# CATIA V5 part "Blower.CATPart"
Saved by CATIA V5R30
Part number: Blower
Bounding box of the stored display mesh (mm): x -55 to 55, y -55 to 55, z -25 to 72.5
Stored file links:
  D:\CADCIM\CATIA\2020\Ch12\c12_catia_v5_6r2019_tut\c12Tut1\Blower.CATPart
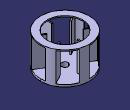
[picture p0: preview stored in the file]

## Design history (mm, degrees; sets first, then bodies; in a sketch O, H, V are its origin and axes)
Body1 (main body)
  Sketch1 on xy-plane, origin (0, 0, 0), H (1, 0, 0), V (0, 1, 0)
    circle A1 centre (0, 0) radius 55
    point P1 (0, 0)
    radius A1 = 55
    coincidence: P1 H, P1 O
  Pad1: profile Sketch1, direction (0, 0, 1), length 5
  Sketch2 on face of Pad1, origin (0, 0, 5), H (1, 0, 0), V (0, 1, 0)
    line L1 (0, 55) -> (0, 30)
    point P1 (0, 55)
    projected arc E1 centre (0, 0) radius 55 from (18.8111, 51.6831) to (0, 55) ccw from edge of Pad1
    line L2 (2.5, 53.4416) -> (2.5, 30)
    arc A1 centre (0, 0) radius 53.5 from (18.2981, 50.2736) to (2.5, 53.4416) ccw
    line L3 (0, 30) -> (2.5, 30)
    line L4 (18.2981, 50.2736) -> (18.8111, 51.6831)
    length L1 = 25
    distance L1 L2 = 2.5
    distance E1 A1 = 1.5
    angle L4 L1 = 20
    coincidence: P1 V, O L4
    vertical: L1 V
    concentricity: E1 A1
    horizontal: L3 H
  Pad2: profile Sketch2, direction (0, 0, 1), length 65
  CircPattern1: of Pad2, instances 6, angular step 60, axis from face of Pad1 from Sketch1.A1
  Sketch3 on face of Pad1, origin (0, 0, 0), H (1, 0, 0), V (0, -1, 0)
    circle A1 centre (0, 0) radius 15
    radius A1 = 15
  Pad3: profile Sketch3, direction (0, 0, -1), length 25
  Sketch4 on face of Pad2, origin (0, 0, 70), H (1, 0, 0), V (0, 1, 0)
    circle A1 centre (0, 0) radius 55
    radius A1 = 55
  Pad4: profile Sketch4, direction (0, 0, 1), length 2.5
  Sketch5 on face of Pad4, origin (0, 0, 72.5), H (1, 0, 0), V (0, 1, 0)
    circle A1 centre (0, 0) radius 40
    circle A2 centre (0, 0) radius 7.5
    radius A2 = 7.5
    radius A1 = 40
  MultiPocket1: profile Sketch5, domains (length 381; length 2.5)
  Sketch6 on yz-plane, origin (0, 0, 0), H (0, 1, 0), V (0, 0, 1)
    line L1 (0, 3.7002) -> (0, 148.5199)
    point P1 (0, 3.7002)
    coincidence: P1 V
    vertical: L1 V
